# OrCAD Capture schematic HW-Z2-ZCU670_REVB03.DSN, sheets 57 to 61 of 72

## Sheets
57 057 UTIL_3V3 15A Regulator: size Custom
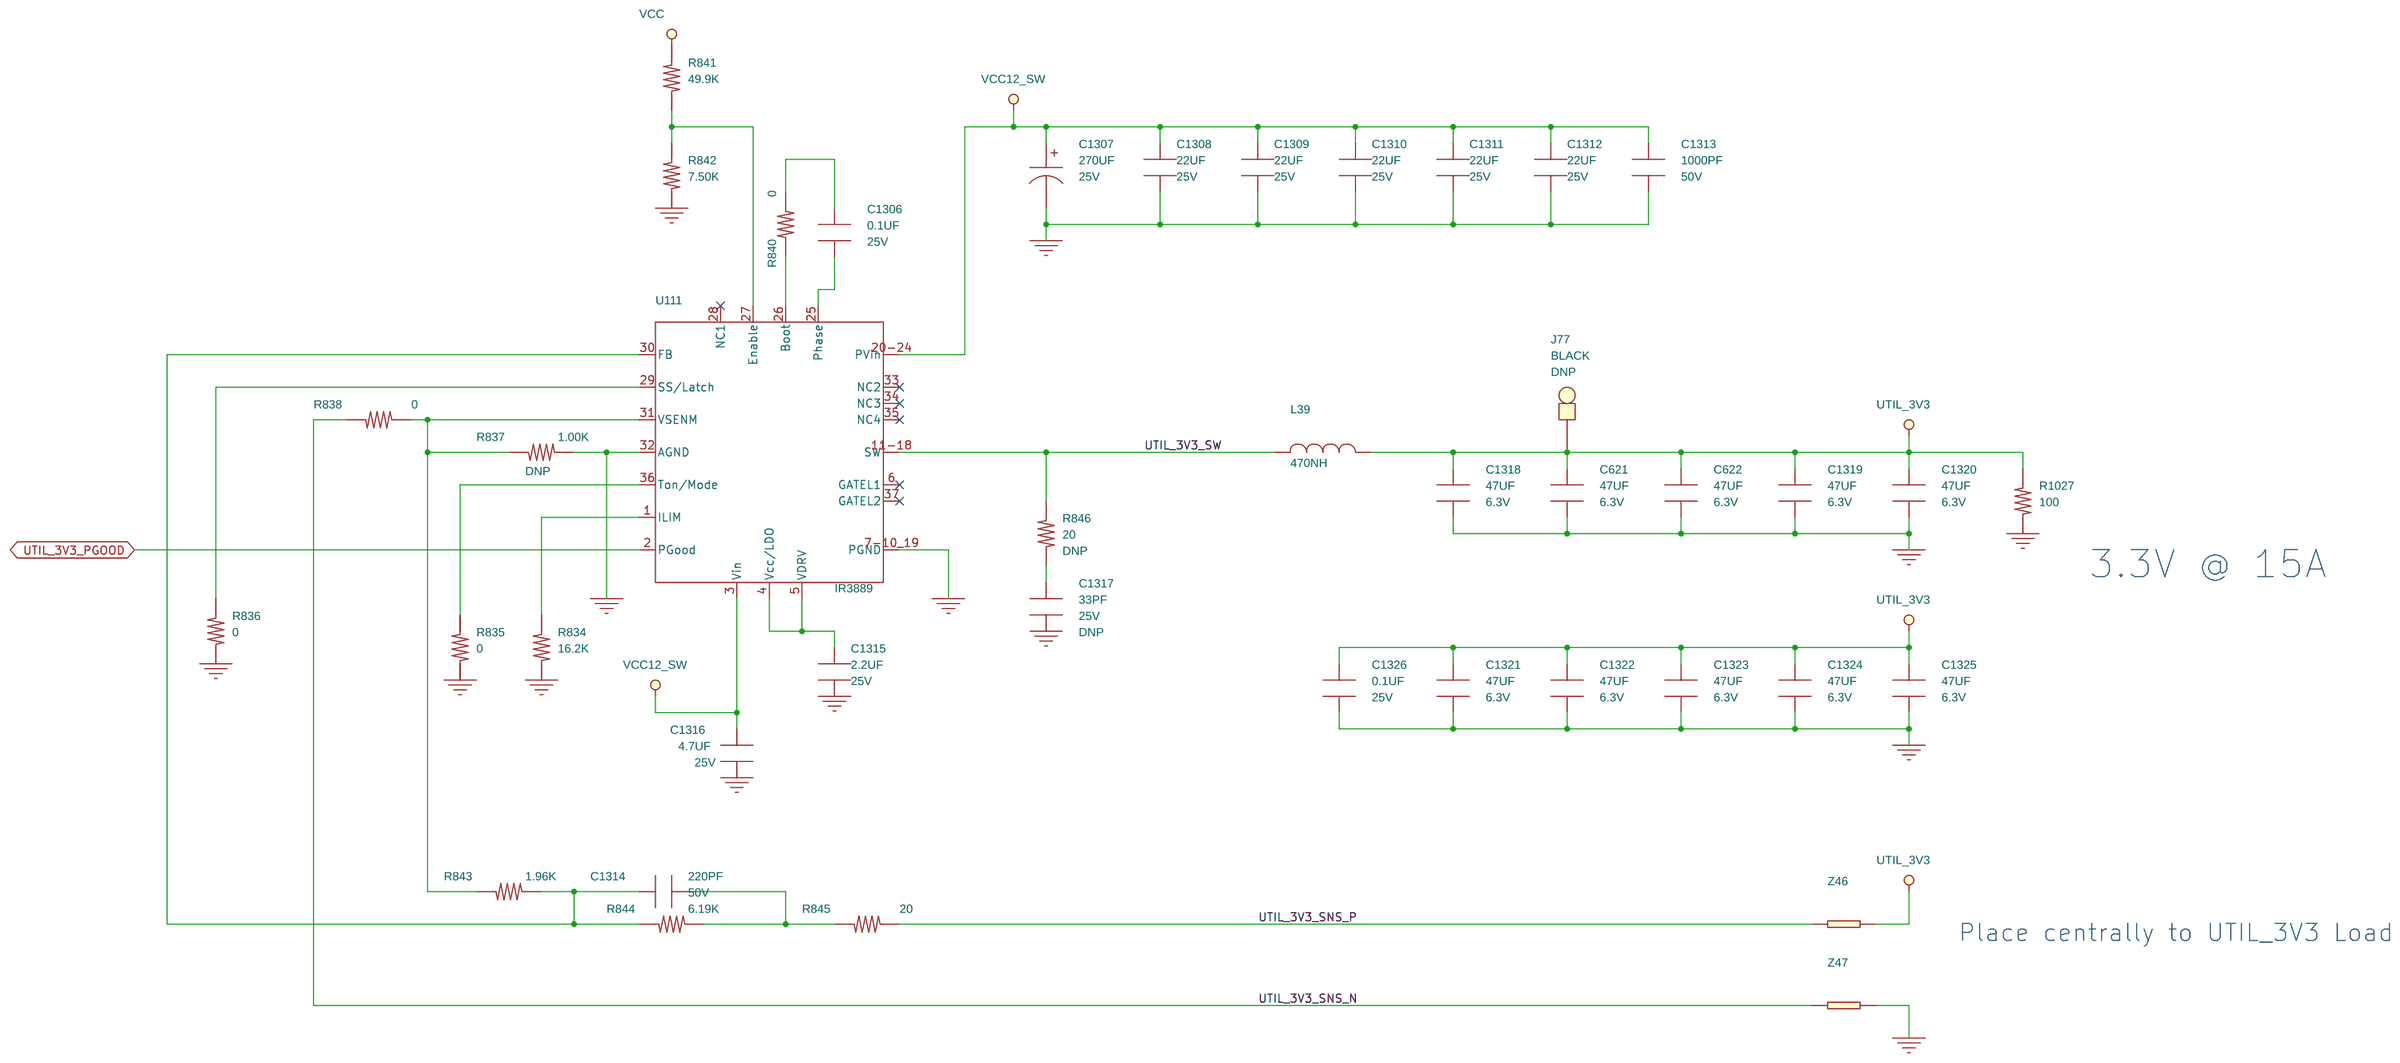
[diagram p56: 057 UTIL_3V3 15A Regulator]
58 058 UTIL_5V0 10A Regulator: size Custom
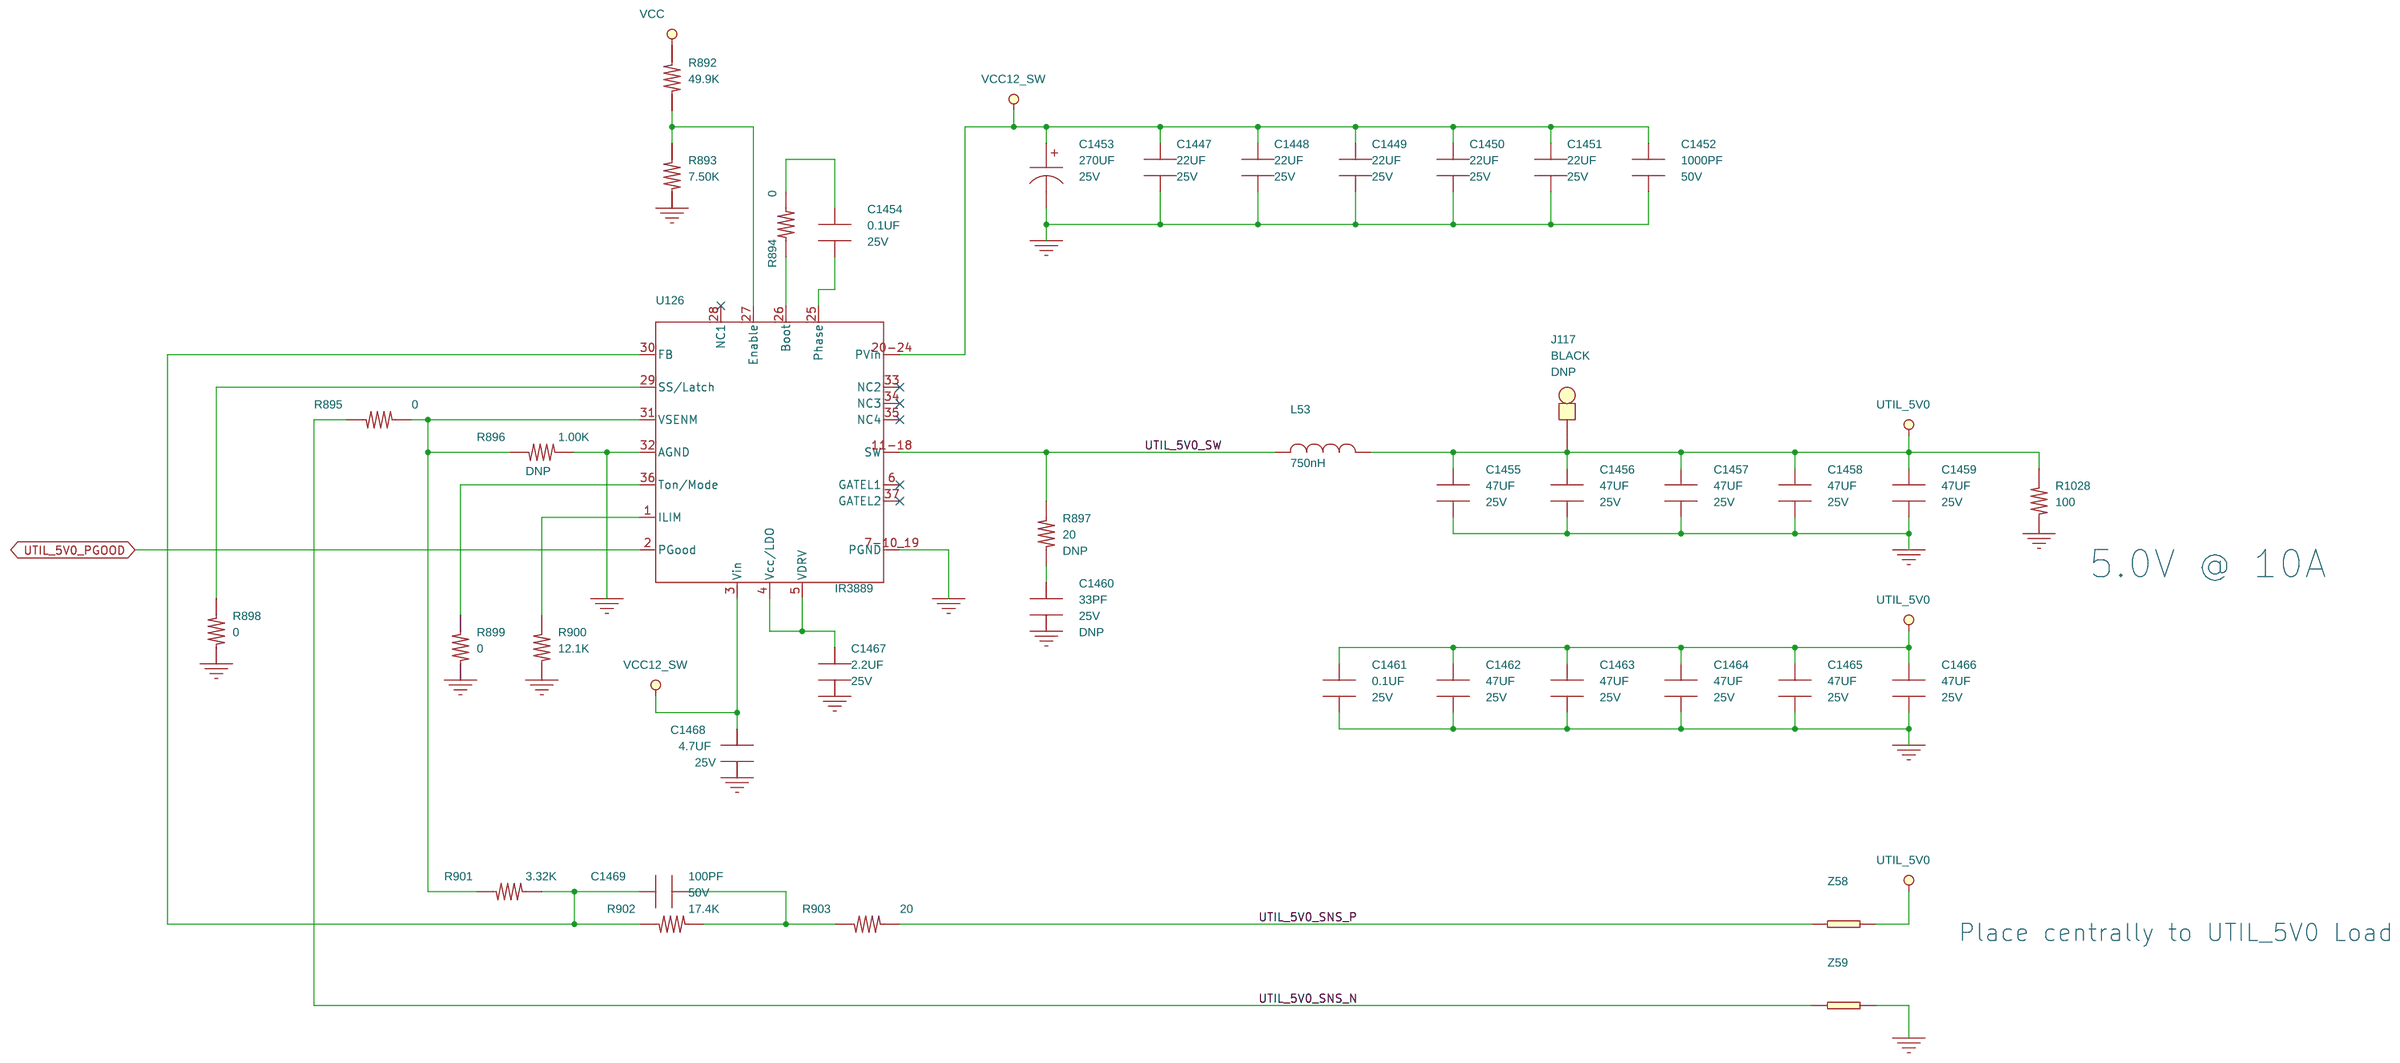
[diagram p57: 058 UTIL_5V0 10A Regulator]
59 059 DDR4 Termination Regulators: size Custom
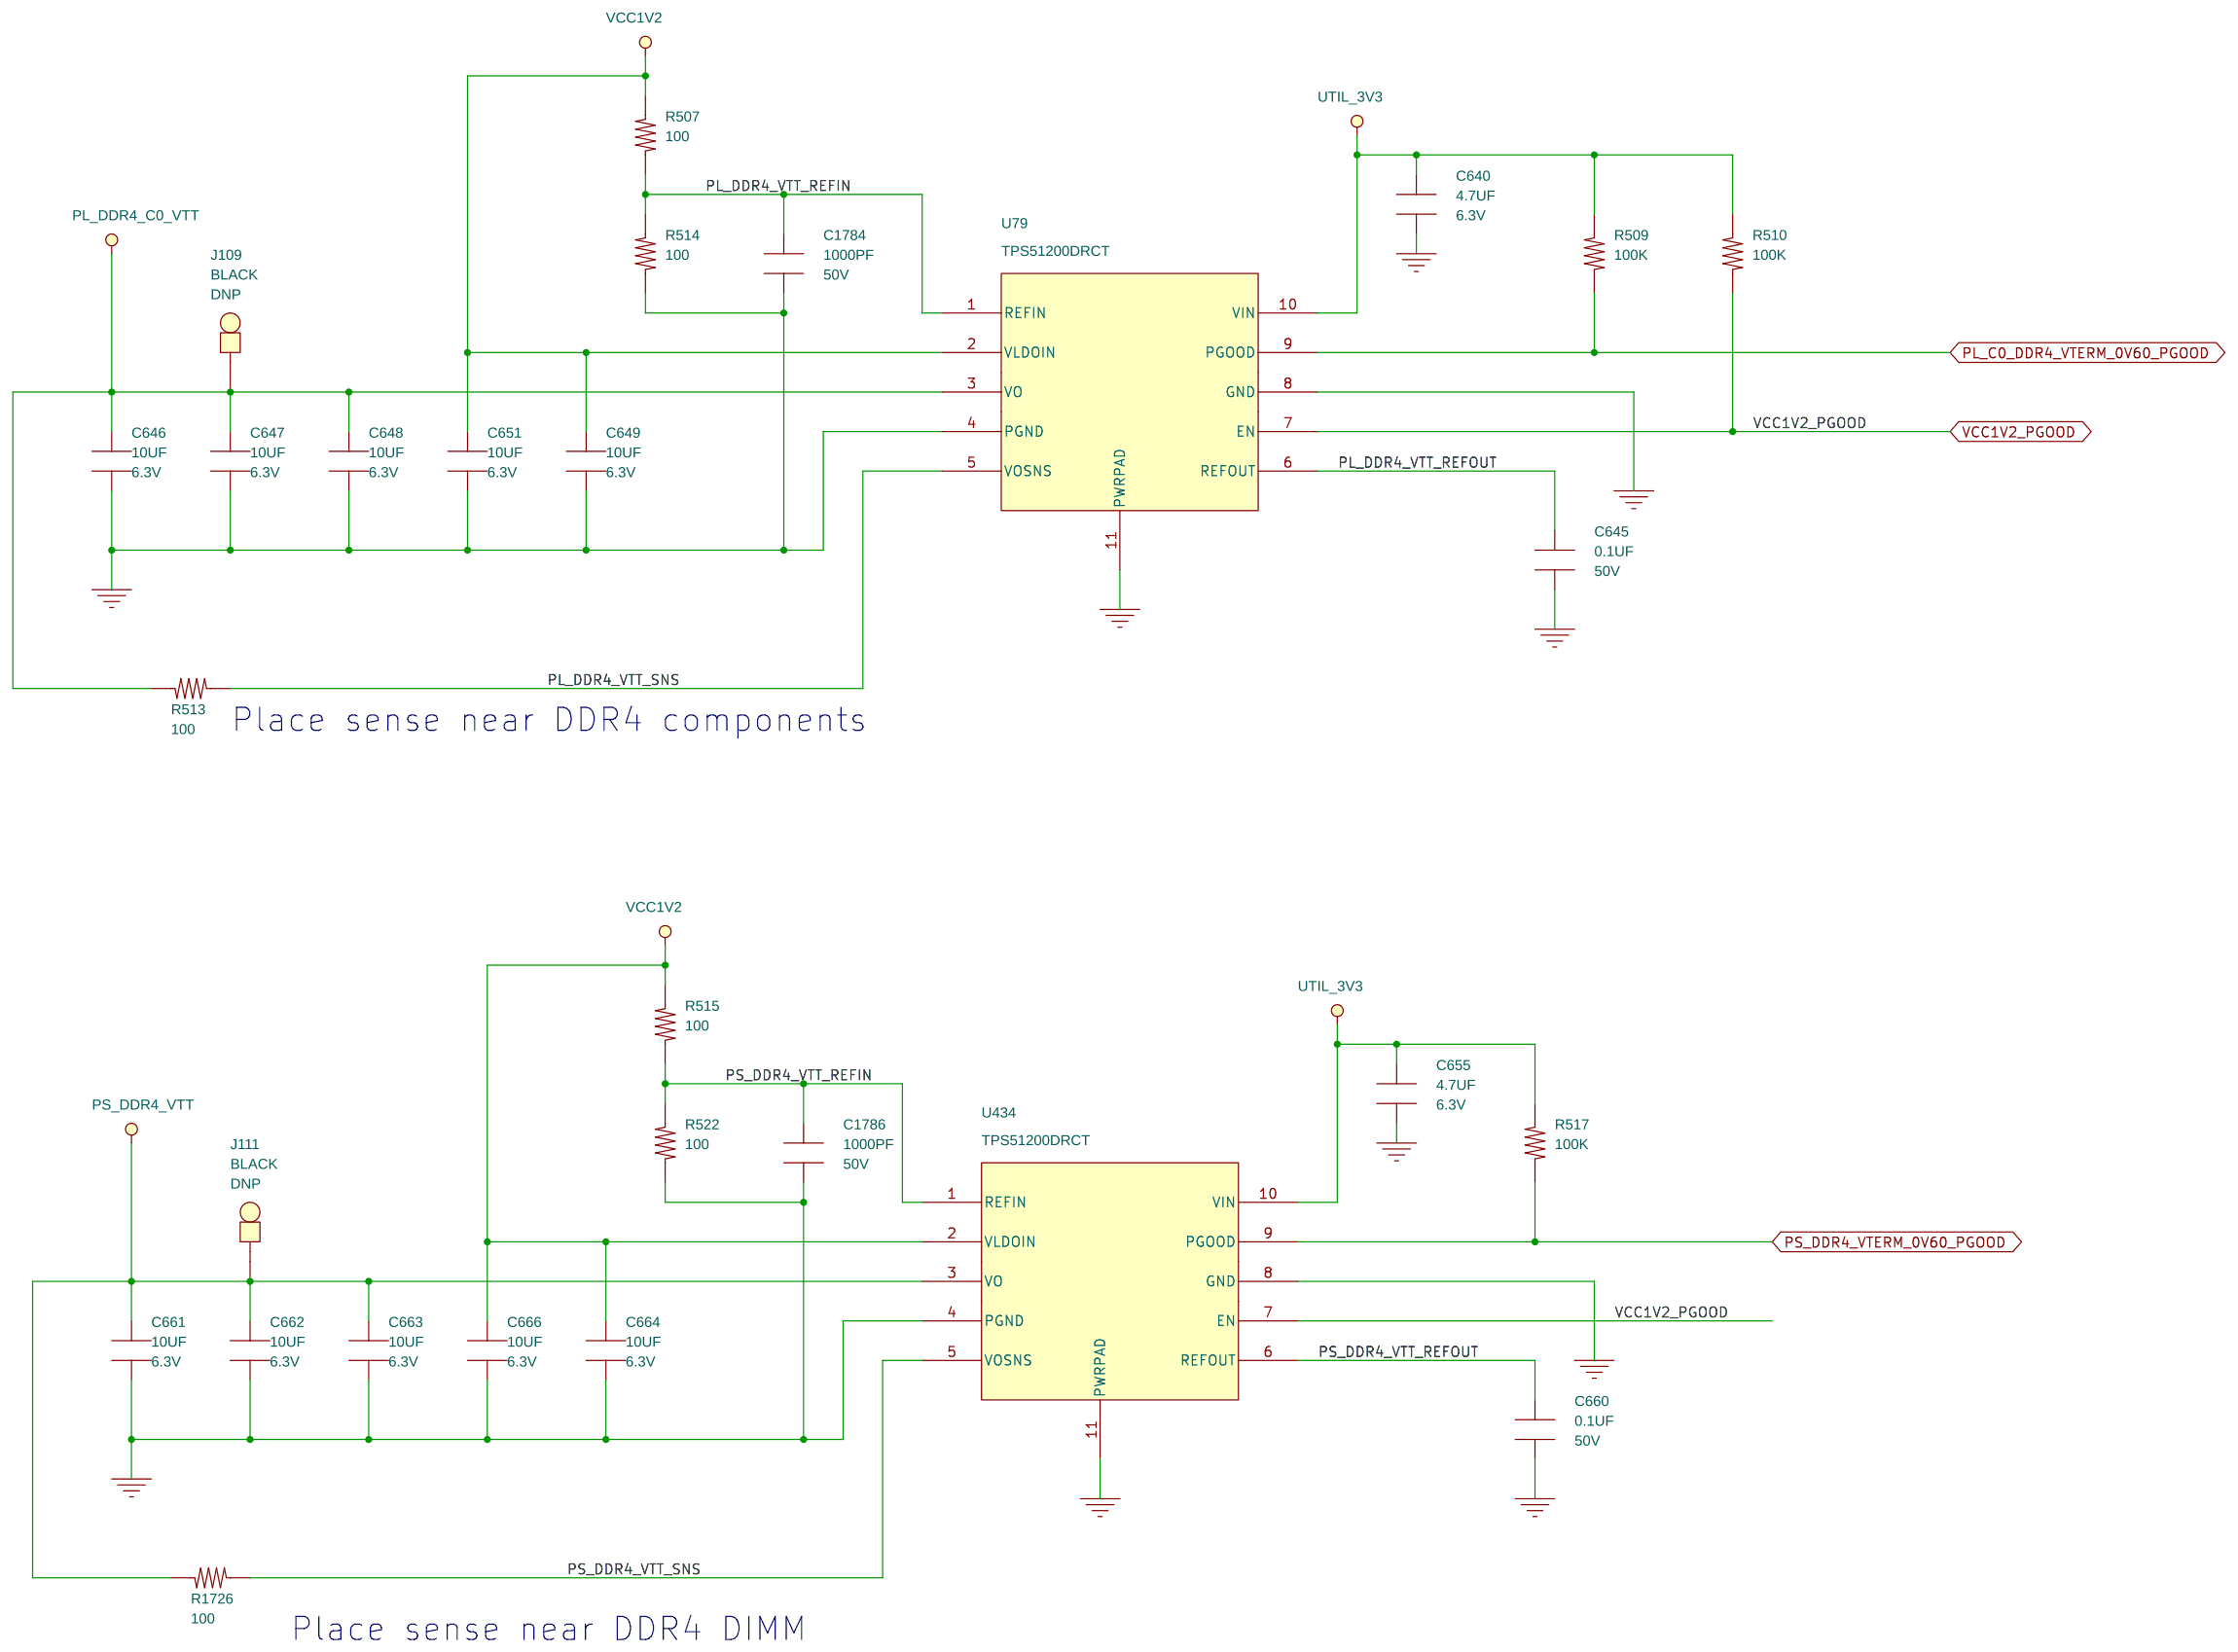
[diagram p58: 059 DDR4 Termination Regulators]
60 060 Power Good LEDs: size Custom
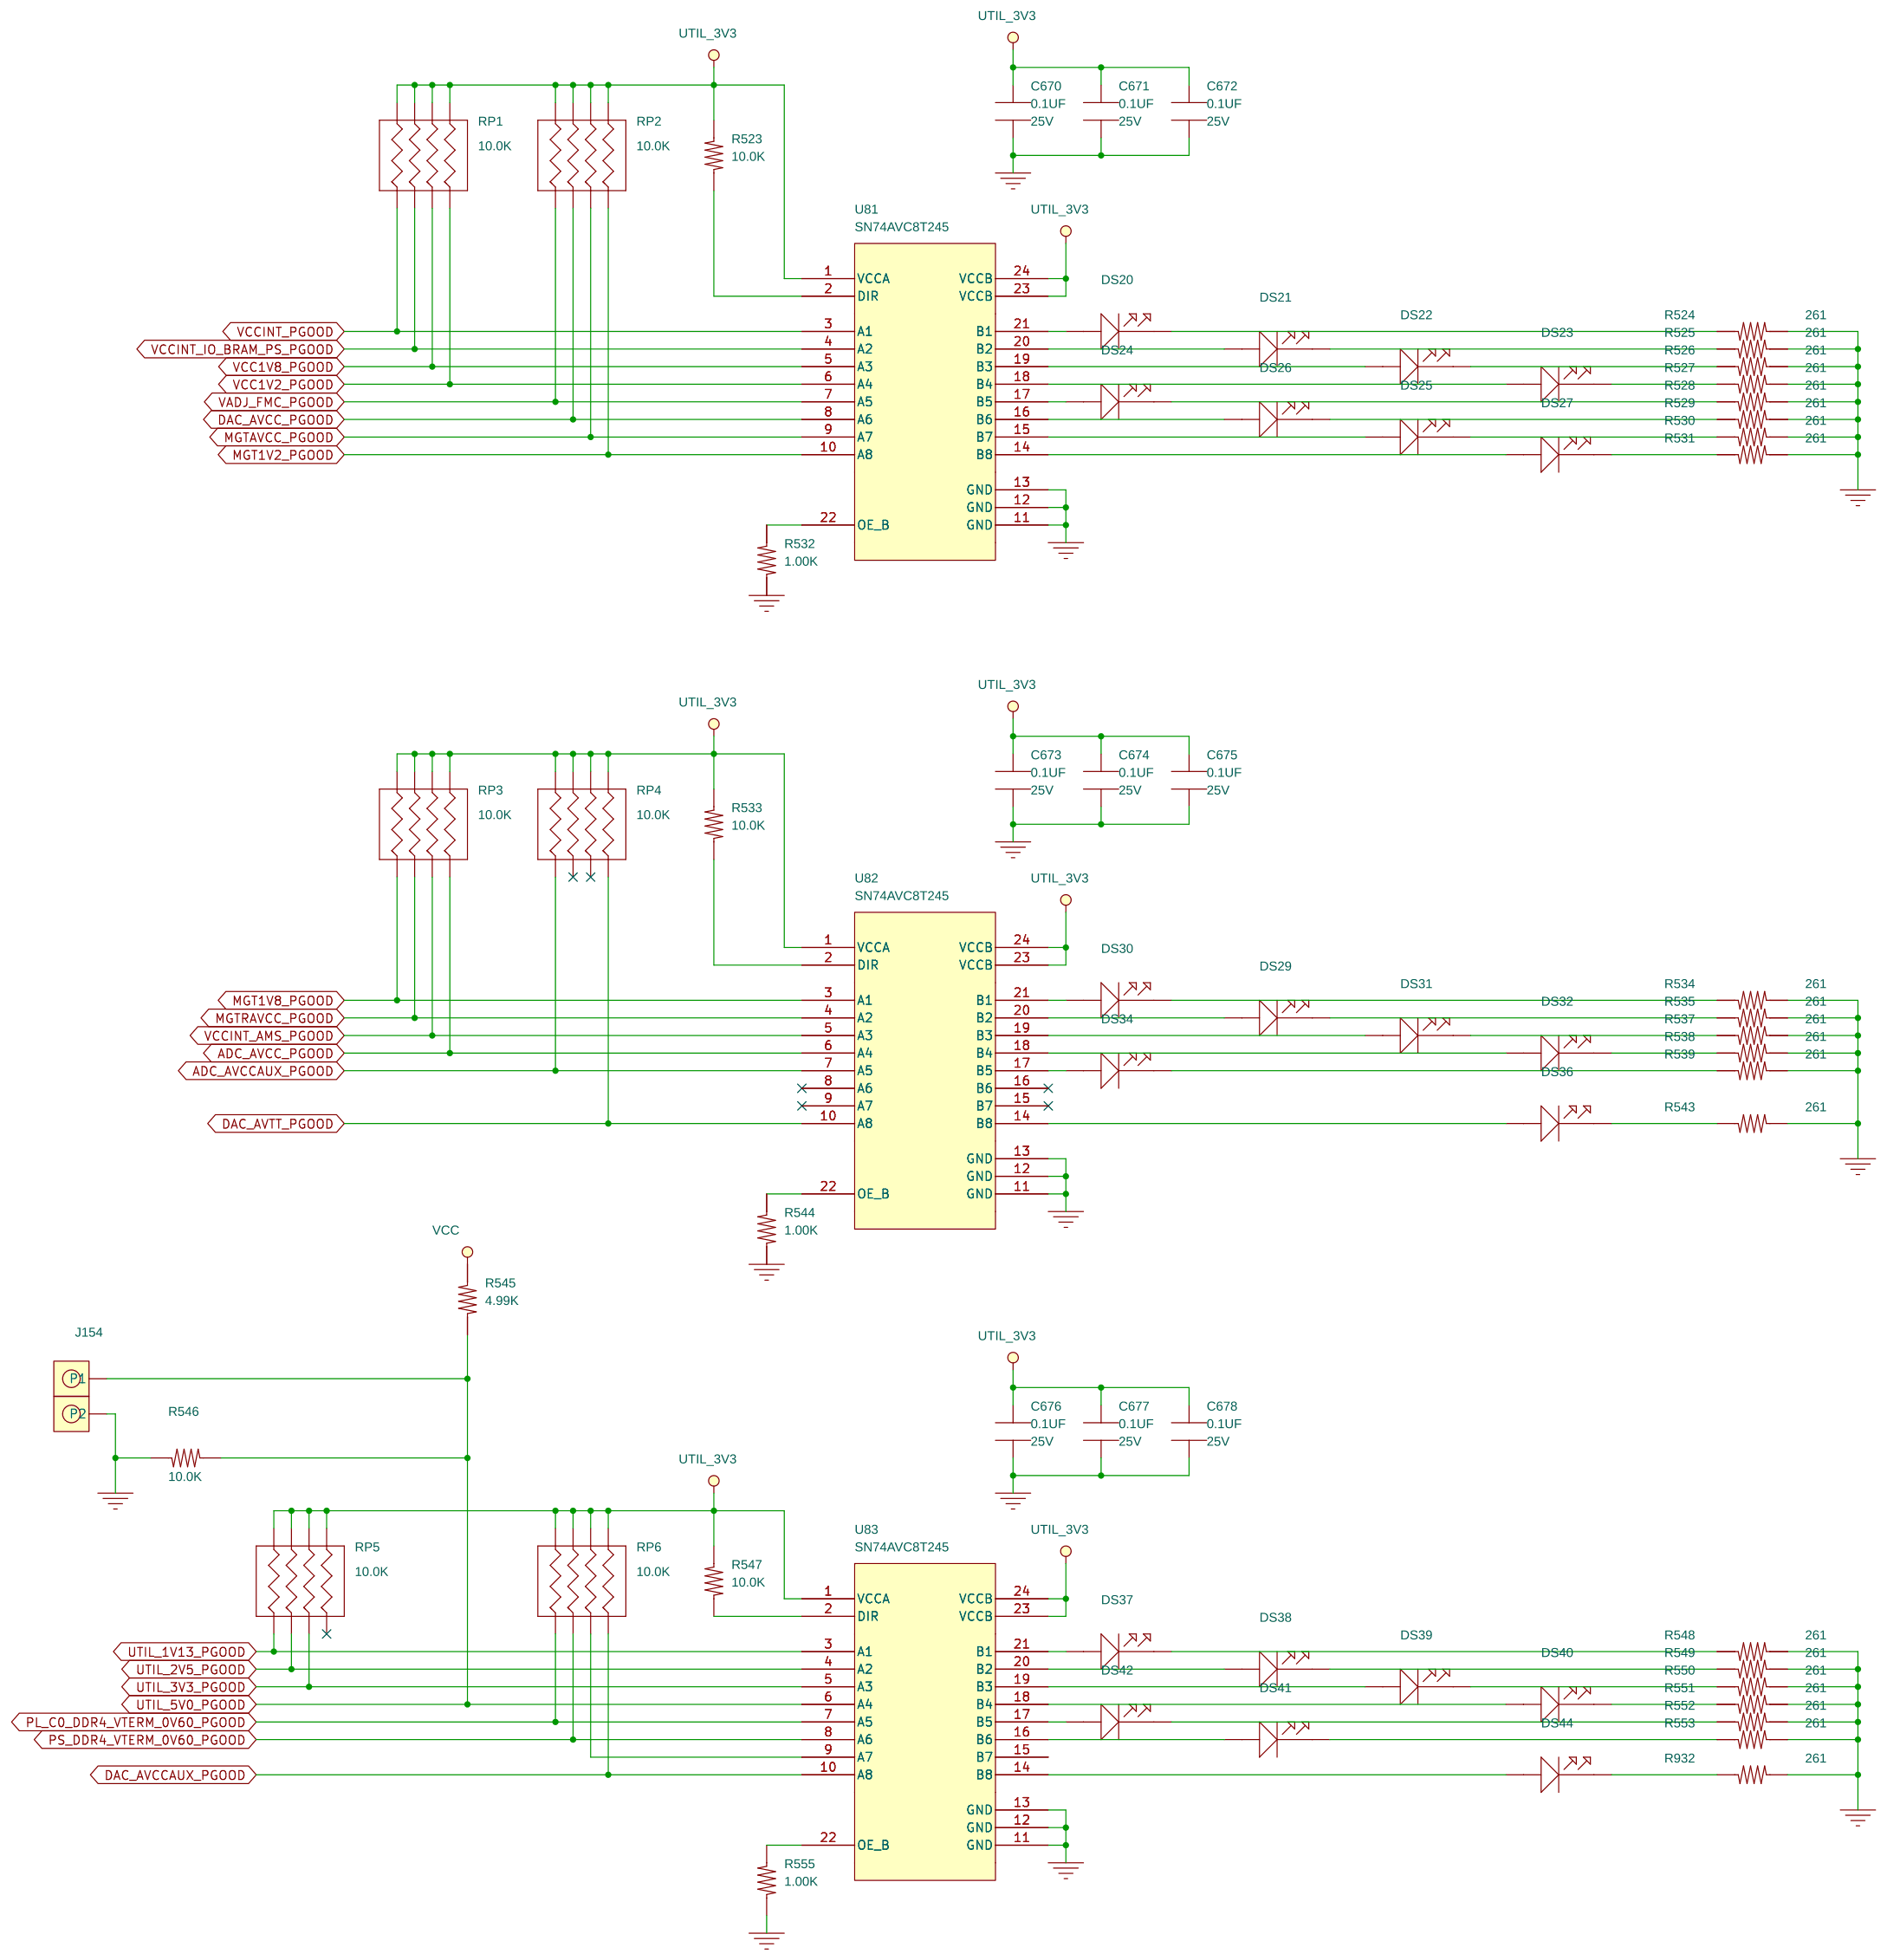
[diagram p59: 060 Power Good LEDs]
61 061 RFMC 2.0 Connector 1: size Custom
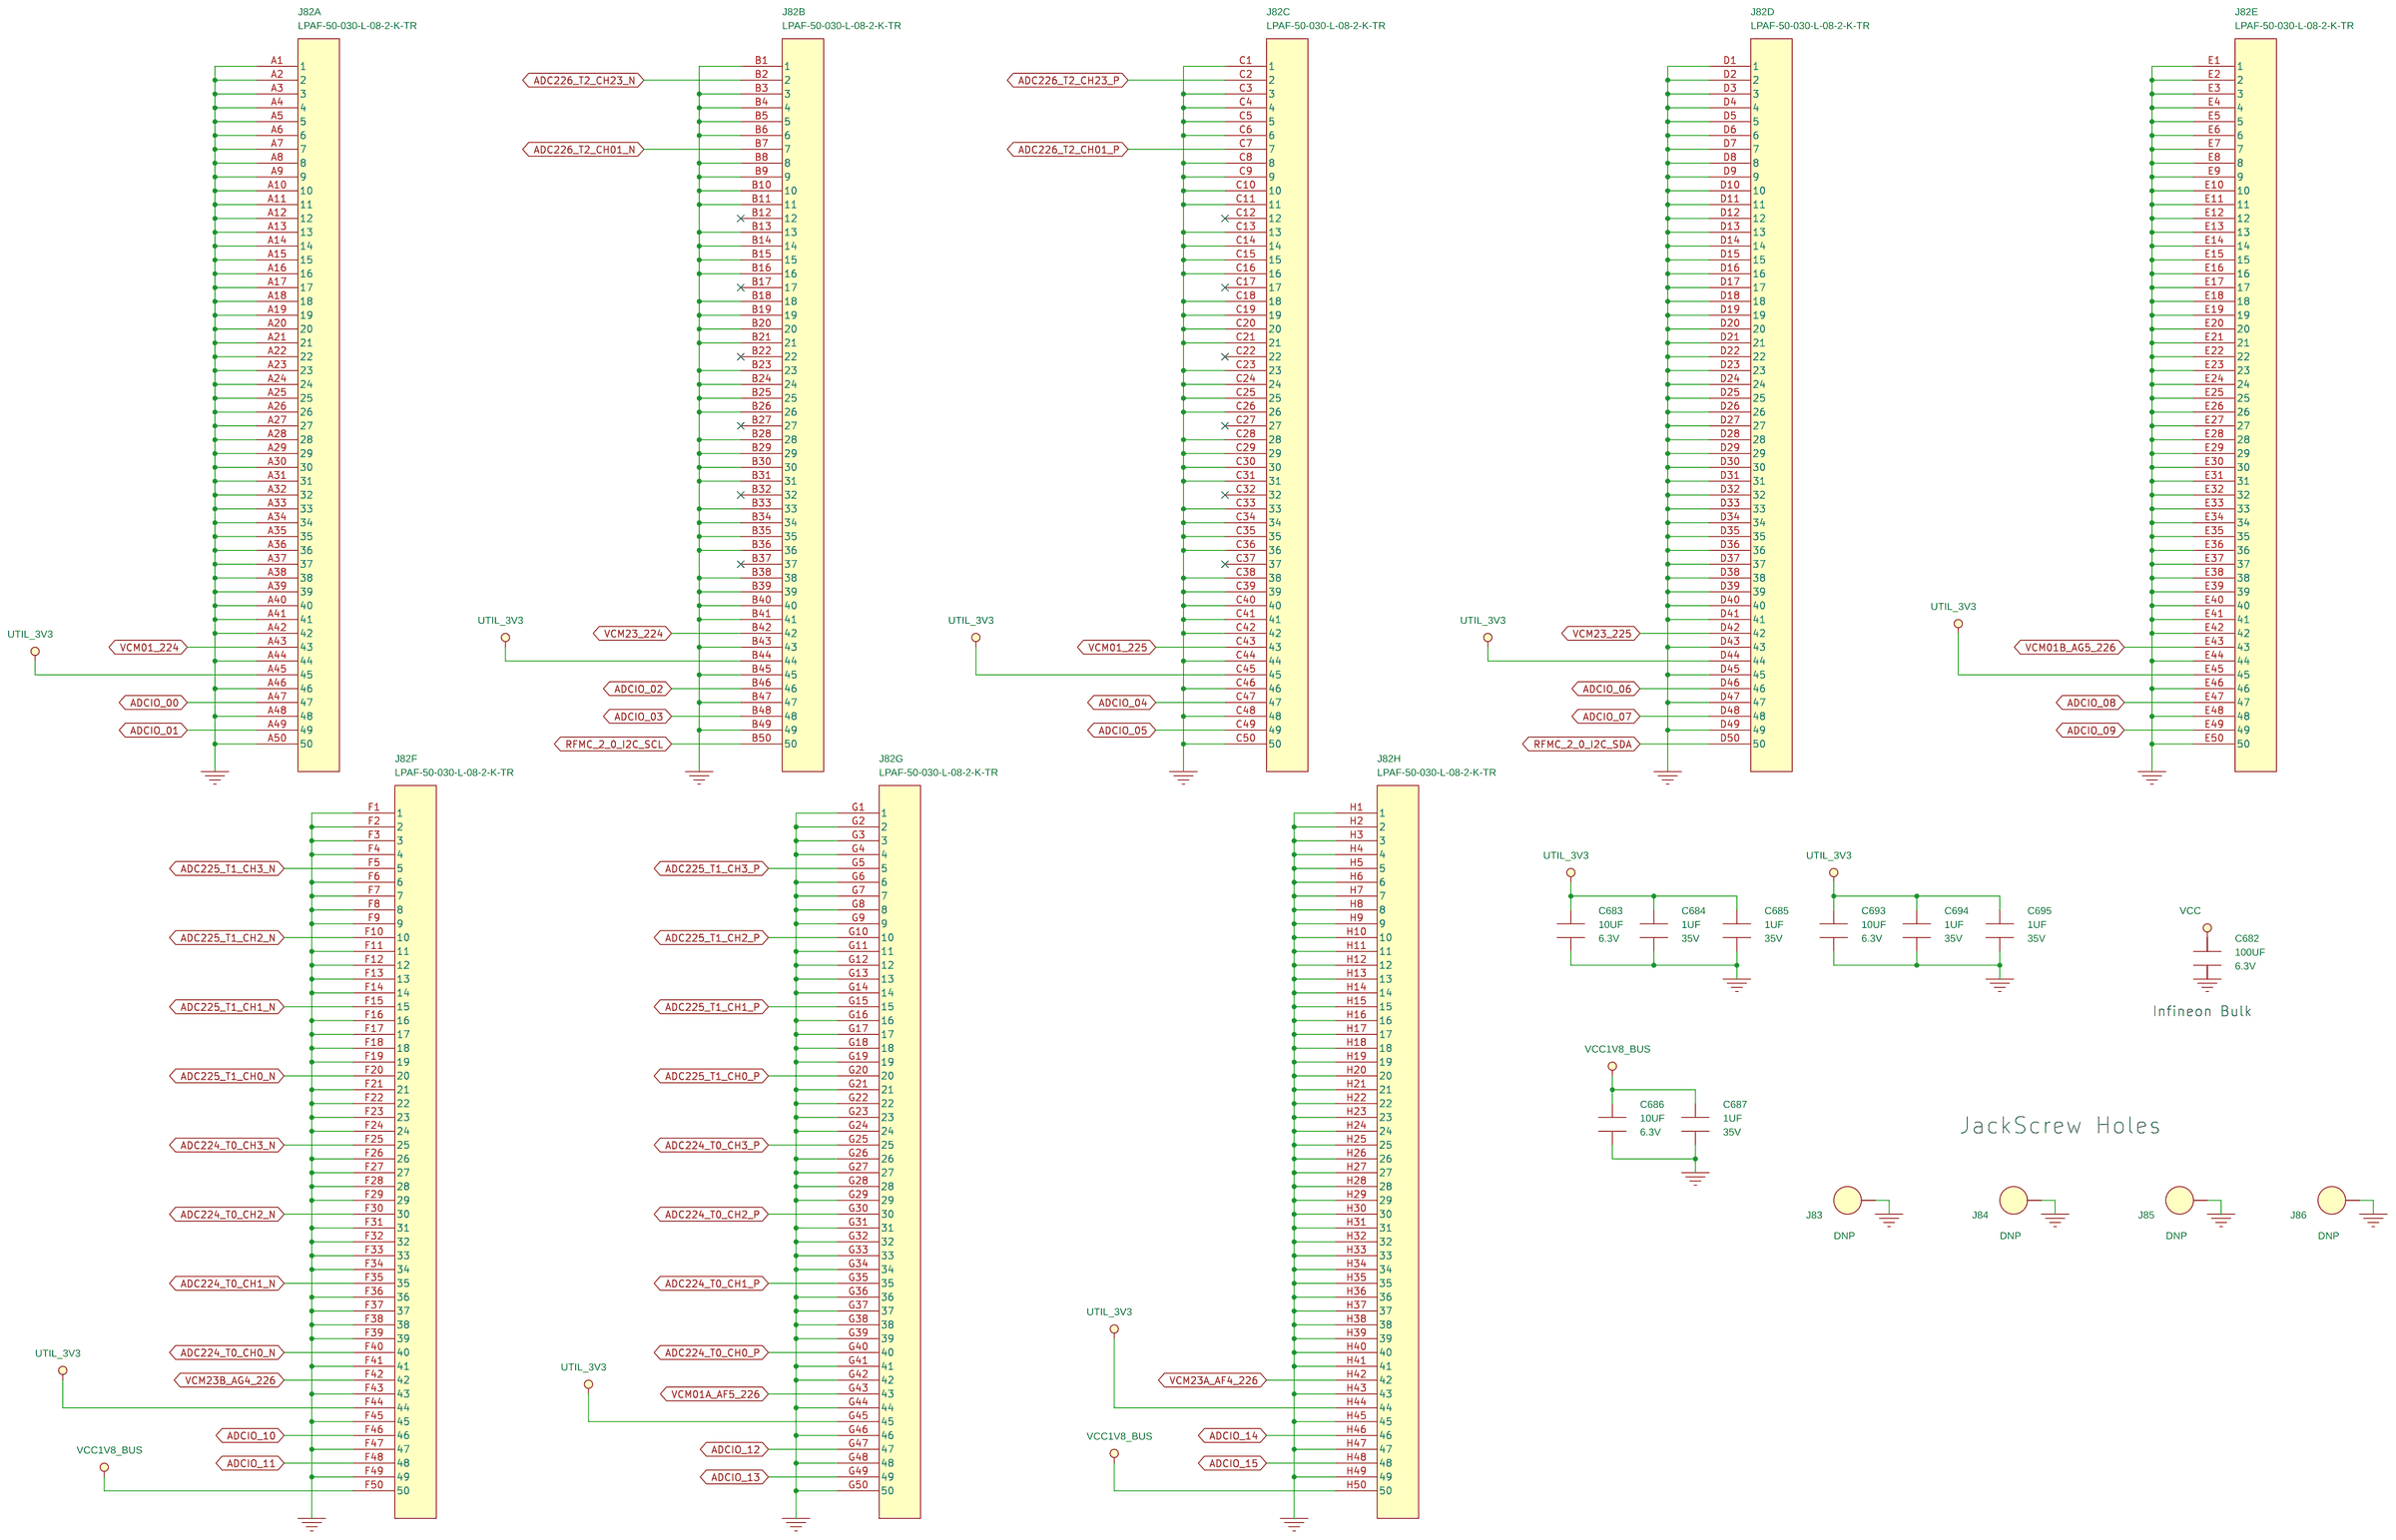
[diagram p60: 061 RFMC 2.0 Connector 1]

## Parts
sheet 057 UTIL_3V3 15A Regulator
C621  47UF  [CAPC200X125X145]
C622  47UF  [CAPC200X125X145]
C1306  0.1UF  [CAPC100X50X55]
C1307  270UF  [CAPR_800_350]
C1308  22UF  [CAPC320X160X180]
C1309  22UF  [CAPC320X160X180]
C1310  22UF  [CAPC320X160X180]
C1311  22UF  [CAPC320X160X180]
C1312  22UF  [CAPC320X160X180]
C1313  1000PF  [CAPC100X50X55]
C1314  220PF  [CAPC100X50X55]
C1315  2.2UF  [CAPC200X125X135]
C1316  4.7UF  [CAPC160X80X100]
C1317  33PF  [CAPC100X50X60]
C1318  47UF  [CAPC200X125X145]
C1319  47UF  [CAPC200X125X145]
C1320  47UF  [CAPC200X125X145]
C1321  47UF  [CAPC200X125X145]
C1322  47UF  [CAPC200X125X145]
C1323  47UF  [CAPC200X125X145]
C1324  47UF  [CAPC200X125X145]
C1325  47UF  [CAPC200X125X145]
C1326  0.1UF  [CAPC100X50X55]
J77  BLACK  [TP_KEY_MINI]
L39  470NH  [IND_WURTH_744355047]
R834  16.2K  [RESC100X50X40]
R835  0  [RESC100X50X40]
R836  0  [RESC100X50X40]
R837  1.00K  [RESC100X50X40]
R838  0  [RESC100X50X40]
R840  0  [RESC100X50X40]
R841  49.9K  [RESC100X50X40]
R842  7.50K  [RESC100X50X40]
R843  1.96K  [RESC100X50X40]
R844  6.19K  [RESC100X50X40]
R845  20  [RESC100X50X40]
R846  20  [RESC100X50X40]
R1027  100  [RESC100X50X40]
U111  IR3889  [QFN_IR3889_36]
Z46  0201_SHORT  [0201_SHORT]
Z47  0201_SHORT  [0201_SHORT]
sheet 058 UTIL_5V0 10A Regulator
C1447  22UF  [CAPC320X160X180]
C1448  22UF  [CAPC320X160X180]
C1449  22UF  [CAPC320X160X180]
C1450  22UF  [CAPC320X160X180]
C1451  22UF  [CAPC320X160X180]
C1452  1000PF  [CAPC100X50X55]
C1453  270UF  [CAPR_800_350]
C1454  0.1UF  [CAPC100X50X55]
C1455  47UF  [CAPC320X160X180]
C1456  47UF  [CAPC320X160X180]
C1457  47UF  [CAPC320X160X180]
C1458  47UF  [CAPC320X160X180]
C1459  47UF  [CAPC320X160X180]
C1460  33PF  [CAPC100X50X60]
C1461  0.1UF  [CAPC100X50X55]
C1462  47UF  [CAPC320X160X180]
C1463  47UF  [CAPC320X160X180]
C1464  47UF  [CAPC320X160X180]
C1465  47UF  [CAPC320X160X180]
C1466  47UF  [CAPC320X160X180]
C1467  2.2UF  [CAPC200X125X135]
C1468  4.7UF  [CAPC160X80X100]
C1469  100PF  [CAPC100X50X55]
J117  BLACK  [TP_KEY_MINI]
L53  750nH  [IND_ABRACON_F1040]
R892  49.9K  [RESC100X50X40]
R893  7.50K  [RESC100X50X40]
R894  0  [RESC100X50X40]
R895  0  [RESC100X50X40]
R896  1.00K  [RESC100X50X40]
R897  20  [RESC100X50X40]
R898  0  [RESC100X50X40]
R899  0  [RESC100X50X40]
R900  12.1K  [RESC100X50X40]
R901  3.32K  [RESC100X50X40]
R902  17.4K  [RESC100X50X40]
R903  20  [RESC100X50X40]
R1028  100  [RESC100X50X40]
U126  IR3889  [QFN_IR3889_36]
Z58  0201_SHORT  [0201_SHORT]
Z59  0201_SHORT  [0201_SHORT]
sheet 059 DDR4 Termination Regulators
C640  4.7UF  [CAPC100X50X70]
C645  0.1UF  [CAPC100X50X55]
C646  10UF  [CAPC100X50X70]
C647  10UF  [CAPC100X50X70]
C648  10UF  [CAPC100X50X70]
C649  10UF  [CAPC100X50X70]
C651  10UF  [CAPC100X50X70]
C655  4.7UF  [CAPC100X50X70]
C660  0.1UF  [CAPC100X50X55]
C661  10UF  [CAPC100X50X70]
C662  10UF  [CAPC100X50X70]
C663  10UF  [CAPC100X50X70]
C664  10UF  [CAPC100X50X70]
C666  10UF  [CAPC100X50X70]
C1784  1000PF  [CAPC100X50X55]
C1786  1000PF  [CAPC100X50X55]
J109  BLACK  [TP_KEY_MINI]
J111  BLACK  [TP_KEY_MINI]
R507  100  [RESC100X50X40]
R509  100K  [RESC100X50X40]
R510  100K  [RESC100X50X40]
R513  100  [RESC60X30X26]
R514  100  [RESC100X50X40]
R515  100  [RESC100X50X40]
R517  100K  [RESC100X50X40]
R522  100  [RESC100X50X40]
R1726  100  [RESC60X30X26]
U79  TPS51200DRCT  [SON50P300X300X100-10TP]
U434  TPS51200DRCT  [SON50P300X300X100-10TP]
sheet 060 Power Good LEDs
C670  0.1UF  [CAPC100X50X55]
C671  0.1UF  [CAPC100X50X55]
C672  0.1UF  [CAPC100X50X55]
C673  0.1UF  [CAPC100X50X55]
C674  0.1UF  [CAPC100X50X55]
C675  0.1UF  [CAPC100X50X55]
C676  0.1UF  [CAPC100X50X55]
C677  0.1UF  [CAPC100X50X55]
C678  0.1UF  [CAPC100X50X55]
DS20  LED-GRN-SMT  [LED_0603]
DS21  LED-GRN-SMT  [LED_0603]
DS22  LED-GRN-SMT  [LED_0603]
DS23  LED-GRN-SMT  [LED_0603]
DS24  LED-GRN-SMT  [LED_0603]
DS25  LED-GRN-SMT  [LED_0603]
DS26  LED-GRN-SMT  [LED_0603]
DS27  LED-GRN-SMT  [LED_0603]
DS29  LED-GRN-SMT  [LED_0603]
DS30  LED-GRN-SMT  [LED_0603]
DS31  LED-GRN-SMT  [LED_0603]
DS32  LED-GRN-SMT  [LED_0603]
DS34  LED-GRN-SMT  [LED_0603]
DS36  LED-GRN-SMT  [LED_0603]
DS37  LED-GRN-SMT  [LED_0603]
DS38  LED-GRN-SMT  [LED_0603]
DS39  LED-GRN-SMT  [LED_0603]
DS40  LED-GRN-SMT  [LED_0603]
DS41  LED-GRN-SMT  [LED_0603]
DS42  LED-GRN-SMT  [LED_0603]
DS44  LED-GRN-SMT  [LED_0603]
J154  HDR_1X2  [HDR_1X2]
R523  10.0K  [RESC100X50X40]
R524  261  [RESC100X50X40]
R525  261  [RESC100X50X40]
R526  261  [RESC100X50X40]
R527  261  [RESC100X50X40]
R528  261  [RESC100X50X40]
R529  261  [RESC100X50X40]
R530  261  [RESC100X50X40]
R531  261  [RESC100X50X40]
R532  1.00K  [RESC100X50X40]
R533  10.0K  [RESC100X50X40]
R534  261  [RESC100X50X40]
R535  261  [RESC100X50X40]
R537  261  [RESC100X50X40]
R538  261  [RESC100X50X40]
R539  261  [RESC100X50X40]
R543  261  [RESC100X50X40]
R544  1.00K  [RESC100X50X40]
R545  4.99K  [RESC100X50X40]
R546  10.0K  [RESC100X50X40]
R547  10.0K  [RESC100X50X40]
R548  261  [RESC100X50X40]
R549  261  [RESC100X50X40]
R550  261  [RESC100X50X40]
R551  261  [RESC100X50X40]
R552  261  [RESC100X50X40]
R553  261  [RESC100X50X40]
R555  1.00K  [RESC100X50X40]
R932  261  [RESC100X50X40]
RP1  10.0K  [RP_EXB_0603x4]
RP2  10.0K  [RP_EXB_0603x4]
RP3  10.0K  [RP_EXB_0603x4]
RP4  10.0K  [RP_EXB_0603x4]
RP5  10.0K  [RP_EXB_0603x4]
RP6  10.0K  [RP_EXB_0603x4]
U81  SN74AVC8T245  [TSSOP_24]
U82  SN74AVC8T245  [TSSOP_24]
U83  SN74AVC8T245  [TSSOP_24]
sheet 061 RFMC 2.0 Connector 1
C682  100UF  [CAPC320X160X180]
C683  10UF  [CAPC100X50X70]
C684  1UF  [CAPC100X50X60]
C685  1UF  [CAPC100X50X60]
C686  10UF  [CAPC100X50X70]
C687  1UF  [CAPC100X50X60]
C693  10UF  [CAPC100X50X70]
C694  1UF  [CAPC100X50X60]
C695  1UF  [CAPC100X50X60]
J82  LPAF-50-030-L-08-2-K-TR  [SAMTEC_LPAF_50_030_L_08_2_K_TR]  (sections A,B,C,D,E,F,G,H)
J83  JSO_0415_01_PRESS_FIT  [JSO_0415_01_PRESS_FIT]
J84  JSO_0415_01_PRESS_FIT  [JSO_0415_01_PRESS_FIT]
J85  JSO_0415_01_PRESS_FIT  [JSO_0415_01_PRESS_FIT]
J86  JSO_0415_01_PRESS_FIT  [JSO_0415_01_PRESS_FIT]

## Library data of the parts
C621 C622 C1318-C1325 = CAP_NP: Cap Cer 47uF 20% 6.3V X5R 0805; Agile Part Number: CAP-00046-01; CIP Link: http://xsjbrdwin1/CIP-E/Component/Index/All?pn=100005; Dielectric Type: X5R; OWNER: 3709; PRICE: 0.17; Part Type: CERAMIC; PartType: CERAMIC; ROHS: Yes; Tolerance: 20%; Voltage: 6.3V; barcode: 100005
C670-C678 C1306 C1326 C1454 C1461 = CAP_NP: Cap Cer 100nF 10% 25V X5R 0402; ALT_SYMBOLS: CAPC100X50X55RND; Agile Part Number: CAP-00068-01; CIP Link: http://xsjbrdwin1/CIP-E/Component/Index/All?pn=100040; Dielectric Type: X5R; OWNER: 4001; PRICE: 0.01; Part Type: CERAMIC; PartType: CERAMIC; ROHS: Yes; Tolerance: 10%; Voltage: 25V; barcode: 100040
C1307 C1453 = CAP_P: Cap Poly 270uF 20% 25V 16mR 8x12mm TH; Agile Part Number: CAP-00226-01; Barcode: 100300; CIP Link: http://xsjbrdwin1/CIP-E/Component/Index/All?pn=100300; Dielectric Type: ELEC; Equivalent Series Resistance: 16mohms; Part Type: ELECTROLYTIC; Tolerance: 20%; Voltage: 25V
C1308-C1312 C1447-C1451 = CAP_NP: Cap Cer 22uF 10% 25V X5R 1206; ALT_SYMBOLS: CAPC320X160X180RND; Agile Part Number: CAP-00058-01; CIP Link: http://xsjbrdwin1/CIP-E/Component/Index/All?pn=100026; Dielectric Type: X5R; OWNER: 3709; PRICE: 0.17; Part Type: CERAMIC; PartType: CERAMIC; ROHS: Yes; Tolerance: 10%; Voltage: 25V; barcode: 100026
C1313 C1452 C1784 C1786 = CAP_NP: Cap Cer 1nF 10% 50V X7R 0402; ALT_SYMBOLS: CAPC100X50X55RND; Agile Part Number: CAP-00036-01; Barcode: 100013; CIP Link: http://xsjbrdwin1/CIP-E/Component/Index/All?pn=100013; Dielectric Type: X7R; Part Type: CERAMIC; Tolerance: 10%; Voltage: 50V
C1314 = CAP_NP: Cap Cer 220pF 10% 50V X7R 0402; ALT_SYMBOLS: (0402,C402-25,CAPC100X50X55L25NRND,CAPC100X50X55L30NRND,CAPC100X50X55L30N); Agile Part Number: CAP-00141-01; Barcode: 100157; CIP Link: http://xsjbrdwin1/CIP-E/Component/Index/All?pn=100157; Dielectric Type: X7R; Part Type: CERAMIC; Tolerance: 10%; Voltage: 50V
C1315 C1467 = CAP_NP: Cap Cer 2.2uF 10% 25V X7R 0805; ALT_SYMBOLS: CAPC200X125X135RND; Agile Part Number: CAP-00114-01; Barcode: 100124; CIP Link: http://xsjbrdwin1/CIP-E/Component/Index/All?pn=100124; Dielectric Type: X7R; Part Type: CERAMIC; Tolerance: 10%; Voltage: 25V
C1316 C1468 = CAP_NP: Cap Cer 4.7uF 10% 25V X5R 0603; ALT_SYMBOLS: 0603; Agile Part Number: CAP-00182-01; Barcode: 100220; CIP Link: http://xsjbrdwin1/CIP-E/Component/Index/All?pn=100220; Dielectric Type: X5R; Part Type: CERAMIC; Tolerance: 10%; Voltage: 25V
C1317 C1460 = CAP_NP: CAP CER 33PF 25V C0G/NP0 0402; ASSEMBLY_OPTIONS: DNP; Agile Part Number: CAP-00086-01; Barcode: 100069; CIP Link: http://xsjbrdwin1/CIP-E/Component/Index/All?pn=100069; Dielectric Type: NP0; Part Type: CERAMIC; Tolerance: 5%; Voltage: 25V
J77 J109 J111 J117 = TP-HOOK: Conn Test Point Mini Loop Black TH; ALT_SYMBOLS: TP_KEY_MINI_DNP; ASSEMBLY_OPTIONS: DNP; Agile Part Number: CON-00272-01; Barcode: 900015; CIP Link: http://xsjbrdwin1/CIP-E/Component/Index/All?pn=900015; OWNER: 3709; Part Type: TEST POINT; PartType: TEST POINT; Pins: 1PIN; Pitch: 0.04IN; ROHS: Yes
L39 = IND: Ind 470nH 20% 26A Irms 50A Isat 99mR 13.0x12.8mm SMT Shielded; Agile Part Number: IND-00146-01; Barcode: 300262; CIP Link: http://xsjbrdwin1/CIP-E/Component/Index/All?pn=300262; OWNER: 3709; PRICE: 0.5; Part Type: POWER INDUCTOR; PartType: POWER INDUCTOR; ROHS: YES; Tolerance: 20%
R834 = RES: Res 16K2 1% 1/16W 100PPM 50V 0402; Agile Part Number: RES-00202-01; Barcode: 200214; CIP Link: http://xsjbrdwin1/CIP-E/Component/Index/All?pn=200214; Part Type: SMT - 1%; Rated Power: 1/16W; Tolerance: 1%
R835 R836 R838 R840 R894 R895 R898 R899 = RES: Res 0R 50mR 1A 0402; ALT_SYMBOLS: RESC100X50X40RND; Agile Part Number: RES-00010-01; Barcode: 200012; CIP Link: http://xsjbrdwin1/CIP-E/Component/Index/All?pn=200012; Part Type: SMT - 5%; Tolerance: 5%
R837 R896 = RES: Res 1K 1% 1/16W 100PPM 50V 0402; ALT_SYMBOLS: RESC100X50X40RND; ASSEMBLY_OPTIONS: DNP; Agile Part Number: RES-00027-01; Barcode: 200098; CIP Link: http://xsjbrdwin1/CIP-E/Component/Index/All?pn=200098; Part Type: SMT - 1%; Rated Power: 1/16W; Tolerance: 1%
R841 R892 = RES: Res 49K9 1% 1/16W 100PPM 50V 0402; ALT_SYMBOLS: RESC100X50X40RND; Agile Part Number: RES-00390-01; Barcode: 200433; CIP Link: http://xsjbrdwin1/CIP-E/Component/Index/All?pn=200433; Part Type: SMT - 1%; Rated Power: 1/16W; Tolerance: 1%
R842 R893 = RES: Res 7K5 1% 1/16W 100PPM 50V 0402; ALT_SYMBOLS: RESC100X50X40RND; Agile Part Number: RES-00008-01; Barcode: 200211; CIP Link: http://xsjbrdwin1/CIP-E/Component/Index/All?pn=200211; Part Type: SMT - 1%; Rated Power: 1/16W; Tolerance: 1%
R843 = RES: Res 1K96 1% 1/16W 100PPM 50V 0402; Agile Part Number: RES-00131-01; Barcode: 200118; CIP Link: http://xsjbrdwin1/CIP-E/Component/Index/All?pn=200118; Part Type: SMT - 1%; Rated Power: 1/16W; Tolerance: 1%
R844 = RES: Res 6K19 1% 1/16W 100PPM 50V 0402; Agile Part Number: RES-00125-01; Barcode: 200112; CIP Link: http://xsjbrdwin1/CIP-E/Component/Index/All?pn=200112; Part Type: SMT - 1%; Rated Power: 1/16W; Tolerance: 1%
R845 R903 = RES: Res 20R 1% 1/16W 100PPM 50V 0402; ALT_SYMBOLS: RESC100X50X40RND; Agile Part Number: RES-00033-01; Barcode: 200119; CIP Link: http://xsjbrdwin1/CIP-E/Component/Index/All?pn=200119; Part Type: SMT - 1%; Rated Power: 1/16W; Tolerance: 1%
R846 R897 = RES: Res 20R 1% 1/16W 100PPM 50V 0402; ALT_SYMBOLS: RESC100X50X40RND; ASSEMBLY_OPTIONS: DNP; Agile Part Number: RES-00033-01; Barcode: 200119; CIP Link: http://xsjbrdwin1/CIP-E/Component/Index/All?pn=200119; Part Type: SMT - 1%; Rated Power: 1/16W; Tolerance: 1%
R1027 R1028 = RES: Res 100R 1% 1/16W 100PPM 50V 0402; ALT_SYMBOLS: RESC100X50X40RND; Agile Part Number: RES-00046-01; Barcode: 200024; CIP Link: http://xsjbrdwin1/CIP-E/Component/Index/All?pn=200024; Part Type: SMT - 1%; Rated Power: 1/16W; Tolerance: 1%
U111 U126 = IR3889: IC V. Reg Step-Down DC/DC Synch 17V 30A 2MHz PQFN-36; Agile Part Number: ICS-00511-01; Barcode: 50000037; CIP Link: http://xsjbrdwin1/CIP-E/Component/Index/All?pn=50000037; Part Type: Integrated Circuits (ICs)\--
Z46 Z47 Z58 Z59 = 0201_SHORT: PCB only 0201_SHORT; ASSEMBLY_OPTIONS: DNP; Barcode: 96000001; CIP Link: http://xsjbrdwin1/CIP-E/Component/Index/All?pn=96000001; OWNER: 3670; Part Type: PCB LAYOUT; PartType: PCB LAYOUT; ROHS: 0
C1455-C1459 C1462-C1466 = CAP_NP: Cap Cer 47uF 20% 25V X5R 1206; ALT_SYMBOLS: CAPC320X160X180RND; Agile Part Number: CAP-00092-01; CIP Link: http://xsjbrdwin1/CIP-E/Component/Index/All?pn=100087; Dielectric Type: X5R; OWNER: 3709; PRICE: 0.17; Part Type: CERAMIC; PartType: CERAMIC; ROHS: Yes; Tolerance: 20%; Voltage: 25V; barcode: 100087
C1469 = CAP_NP: Cap Cer 100pF 5% 50V C0G 0402; ALT_SYMBOLS: CAPC100X50X55RND; Agile Part Number: CAP-00161-01; Barcode: 100187; CIP Link: http://xsjbrdwin1/CIP-E/Component/Index/All?pn=100187; Dielectric Type: NP0; Part Type: CERAMIC; Tolerance: 5%; Voltage: 50V
L53 = IND: Ind 750nH 20% 22A Irms 39A Isat 2.7mR 11x10mm SMT Molded Shielded AEC-Q200; Agile Part Number: IND-00177-01; Barcode: 30000016; CIP Link: http://xsjbrdwin1/CIP-E/Component/Index/All?pn=30000016; OWNER: 3709; PRICE: 0.5; Part Type: Unassigned Part Type; PartType: POWER INDUCTOR; ROHS: YES; Tolerance: 20%
R900 = RES: Res 12K1 1% 1/16W 100PPM 50V 0402; ALT_SYMBOLS: (0402,C402-25,RESC100X50X40L25NRND); Agile Part Number: RES-00016-01; Barcode: 200225; CIP Link: http://xsjbrdwin1/CIP-E/Component/Index/All?pn=200225; Part Type: SMT - 1%; Rated Power: 1/16W; Tolerance: 1%
R901 = RES: Res 3K32 1% 1/16W 100PPM 50V 0402; ALT_SYMBOLS: RESC100X50X40RND; Agile Part Number: RES-00189-01; Barcode: 200198; CIP Link: http://xsjbrdwin1/CIP-E/Component/Index/All?pn=200198; Part Type: SMT - 1%; Rated Power: 1/16W; Tolerance: 1%
R902 = RES: Res 17K4 1% 1/16W 100PPM 50V 0402; Agile Part Number: RES-00229-01; Barcode: 200245; CIP Link: http://xsjbrdwin1/CIP-E/Component/Index/All?pn=200245; Part Type: SMT - 1%; Rated Power: 1/16W; Tolerance: 1%
C640 C655 = CAP_NP: Cap Cer 4.7uF 20% 6.3V X6S 0402; ALT_SYMBOLS: CAPC100X50X70RND; Agile Part Number: CAP-00023-01; CIP Link: http://xsjbrdwin1/CIP-E/Component/Index/All?pn=100230; DEVICE: 4_7UF_0402_X6S_6.3V; Dielectric: X6S; Dielectric Type: X6S; MANF: MURATA; MANF_P/N: GRM155C80J475MEAAD; OWNER: 3709; PRICE: 0.04; Part Type: CERAMIC; PartType: CERAMIC; ROHS: Yes; Tolerance: 20%; Voltage: 6.3V; barcode: 100230; Datasheet: \\XSJ-SMB\AFX\AFX\BOARD_PROJECTS\LIBRARY\\DATASHEETS\CAPACITOR\GRM155C80J475MEAA-01.pdf
C645 C660 = CAP_NP: Cap Cer 100nF 10% 50V X7R 0402; ALT_SYMBOLS: CAPC100X50X55RND; Agile Part Number: CAP-00022-01; CIP Link: http://xsjbrdwin1/CIP-E/Component/Index/All?pn=100170; DEVICE: 0_1UF_0402_X7R_50V; Dielectric: X7R; Dielectric Type: X7R; MANF: TAIYO YUDEN; MANF_P/N: UMK105B7104KV-FR; OWNER: 6176; PRICE: 0.02; Part Type: CERAMIC; PartType: CERAMIC; ROHS: Yes; Tolerance: 10%; Voltage: 50V; barcode: 100170; Datasheet: \\XSJ-SMB\AFX\AFX\BOARD_PROJECTS\LIBRARY\DATASHEETS\CAPACITOR\MLCC_ALL_E.PDF
C646-C649 C651 C661-C664 C666 = CAP_NP: Cap Cer 10uF 20%  6.3V X6S 0402; ALT_SYMBOLS: CAPC100X50X55RND; Agile Part Number: CAP-00035-01; CIP Link: http://xsjbrdwin1/CIP-E/Component/Index/All?pn=100268; DEVICE: 10UF_0402_X6S_6.3V; Dielectric: X6S; Dielectric Type: X6S; MANF: MURATA; MANF_P/N: GRM155C80J106ME11D; OWNER: 13503; PRICE: 0.03; Part Type: CERAMIC; PartType: CERAMIC; ROHS: Yes; Tolerance: 20%; Voltage: 6.3V; barcode: 100268; Datasheet: \\XSJ-SMB\AFX\AFX\BOARD_PROJECTS\LIBRARY\\DATASHEETS\CAPACITOR\GRM155C80J106ME11-01.PDF
R507 R514 R515 R522 = RES: Res 100R 1% 1/16W 100PPM 50V 0402; ALT_SYMBOLS: RESC100X50X40RND; Agile Part Number: RES-00046-01; Barcode: 200024; CIP Link: http://xsjbrdwin1/CIP-E/Component/Index/All?pn=200024; DEVICE: 100_0402_1P; MANF: PANASONIC; MANF_P/N: ERJ-2RKF1000X; OWNER: 4001; PRICE: 0.02; Part Type: SMT - 1%; PartType: SMT - 1%; Power: 1/10W; ROHS: Yes; Rated Power: 1/16W; Tolerance: 1%; primarykey: 403; Datasheet: \\XSJ-SMB\AFX\AFX\BOARD_PROJECTS\LIBRARY\\DATASHEETS\RESISTOR\PANA_ERJ_1%.PDF
R509 R510 R517 = RES: Res 100K 1% 1/16W 100PPM 50V 0402; ALT_SYMBOLS: RESC100X50X40RND; ASSEMBLY_OPTIONS: DNP; Agile Part Number: RES-00011-01; Barcode: 200026; CIP Link: http://xsjbrdwin1/CIP-E/Component/Index/All?pn=200026; DEVICE: 100K_0402_1P; MANF: PANASONIC; MANF_P/N: ERJ-2RKF1003X; OWNER: 3501; PRICE: 0; Part Type: SMT - 1%; PartType: SMT - 1%; Power: 1/10W; ROHS: Yes; Rated Power: 1/16W; Tolerance: 1%; primarykey: 149; Datasheet: \\XSJ-SMB\AFX\AFX\BOARD_PROJECTS\LIBRARY\\DATASHEETS\RESISTOR\PANA_ERJ_1%.PDF
R513 R1726 = RES: Res 100R 1% 1/20W 200PPM 25V 0201; Agile Part Number: RES-00129-01; Barcode: 200116; CIP Link: http://xsjbrdwin1/CIP-E/Component/Index/All?pn=200116; Part Type: SMT - 1%; Rated Power: 1/20W; Tolerance: 1%
U79 U434 = TPS51200: IC Term Reg DDR 4.5A Source 5.5A Sink VSON-10; ALT_SYMBOLS: SON10_TPS51200; Agile Part Number: ICS-00475-01; Barcode: 740011; CIP Link: http://xsjbrdwin1/CIP-E/Component/Index/All?pn=740011; Part Type: REGULATOR
DS20-DS27 DS29-DS32 DS34 DS36-DS42 DS44 = LED: LED Green Diffused 20mA 5V 570nm 0603; Agile Part Number: DIO-00003-01; Barcode: 300021; CIP Link: http://xsjbrdwin1/CIP-E/Component/Index/All?pn=300021; OWNER: 4001; PRICE: 0.1; Power: 2.2-20MA; ROHS: Yes; Rated Power: 2.2-20MA; Voltage: 2.2V
J154 = HDR_1X2: Conn Hdr Male Vert 2 Pos 1x2 2.54mm P Black TH; Agile Part Number: CON-00037-01; Barcode: 390102; CIP Link: http://xsjbrdwin1/CIP-E/Component/Index/All?pn=390102; OWNER: 4001; PRICE: 0.03; Part Type: HEADER; PartType: HEADER; Pins: 2PINS; Pitch: 0.100; ROHS: Yes
R523 R533 R546 R547 = RES: Res 10K 1% 1/16W 100PPM 50V 0402; ALT_SYMBOLS: RESC100X50X40RND; Agile Part Number: RES-00030-01; Barcode: 200025; CIP Link: http://xsjbrdwin1/CIP-E/Component/Index/All?pn=200025; OWNER: 4001; PRICE: 0; Part Type: SMT - 1%; PartType: SMT - 1%; Power: 1/10W; ROHS: Yes; Rated Power: 1/16W; Tolerance: 1%; primarykey: 1
R524-R531 R534 R535 R537-R539 R543 R548-R553 R932 = RES: Res 261R 1% 1/16W 100PPM 50V 0402; ALT_SYMBOLS: RESC100X50X40RND; Agile Part Number: RES-00086-01; Barcode: 200050; CIP Link: http://xsjbrdwin1/CIP-E/Component/Index/All?pn=200050; OWNER: 3501; PRICE: 0; Part Type: SMT - 1%; PartType: SMT - 1%; Power: 1/10W; ROHS: Yes; Rated Power: 1/16W; Tolerance: 1%; primarykey: 60
R532 R544 R555 = RES: Res 1K 1% 1/16W 100PPM 50V 0402; ALT_SYMBOLS: RESC100X50X40RND; Agile Part Number: RES-00027-01; Barcode: 200098; CIP Link: http://xsjbrdwin1/CIP-E/Component/Index/All?pn=200098; OWNER: 4001; PRICE: 0; Part Type: SMT - 1%; PartType: SMT - 1%; Power: 1/16W; ROHS: Yes; Rated Power: 1/16W; Tolerance: 1%; primarykey: 7
R545 = RES: Res 4K99 1% 1/16W 100PPM 50V 0402; ALT_SYMBOLS: RESC100X50X40RND; Agile Part Number: RES-00004-01; Barcode: 200072; CIP Link: http://xsjbrdwin1/CIP-E/Component/Index/All?pn=200072; OWNER: 10460; PRICE: 0; Part Type: SMT - 1%; PartType: SMT - 1%; Power: 1/10W; ROHS: Yes; Rated Power: 1/16W; Tolerance: 1%; primarykey: 157
RP1-RP6 = RPACK_10K_X4: Res Array 4x 10K 5% 1/16W 200PPM 50V 1206 Concave; Agile Part Number: RES-00123-01; Barcode: 200110; CIP Link: http://xsjbrdwin1/CIP-E/Component/Index/All?pn=200110; OWNER: 3501; PRICE: 0.05; Part Type: RPACK; PartType: RPACK; Power: 1/16W; ROHS: Yes; Rated Power: 1/16W; Tolerance: 5%; primarykey: 142
U81-U83 = SN74AVC8T245: IC Lvl Trans 8-Bit Bidir 320Mbps 1.2-3.6V 50mA TSSOP-24; Agile Part Number: ICS-00050-01; Barcode: 500014; CIP Link: http://xsjbrdwin1/CIP-E/Component/Index/All?pn=500014; Family: BUS TRANSCEIVER; Part Type: BUS TRANSCEIVER; ROHS: Yes
C682 = CAP_NP: Cap Cer 100uF 20% 6.3V X5R 1206; ALT_SYMBOLS: 1206; Agile Part Number: CAP-00061-01; CIP Link: http://xsjbrdwin1/CIP-E/Component/Index/All?pn=100029; Dielectric: X6S; Dielectric Type: X5R; OWNER: 3709; PRICE: 0.41; Part Type: CERAMIC; PartType: CERAMIC; ROHS: Yes; Tolerance: 20%; Voltage: 6.3V; barcode: 100029
C683 C686 C693 = CAP_NP: Cap Cer 10uF 20%  6.3V X6S 0402; ALT_SYMBOLS: CAPC100X50X55RND; Agile Part Number: CAP-00035-01; CIP Link: http://xsjbrdwin1/CIP-E/Component/Index/All?pn=100268; Dielectric: X5R; Dielectric Type: X6S; OWNER: 3670; PRICE: 0.04; Part Type: CERAMIC; PartType: CERAMIC; ROHS: Yes; Tolerance: 20%; Voltage: 6.3V; barcode: 100268
C684 C685 C687 C694 C695 = CAP_NP: Cap Cer 1uF 10% 35V X5R 0402; ALT_SYMBOLS: CAPC100X50X60RND; Agile Part Number: CAP-00165-01; CIP Link: http://xsjbrdwin1/CIP-E/Component/Index/All?pn=100192; Dielectric: X5R; Dielectric Type: X5R; OWNER: 3709; PRICE: 0.04; Part Type: CERAMIC; PartType: CERAMIC; ROHS: Yes; Tolerance: 10%; Voltage: 35V; barcode: 100192
J82 = LPAF-50-030-L-08-2-K-TR: Conn Rcpt Female Vert 400 Pos 8x50 1.27mm P Black SMT; Agile Part Number: CON-00235-01; Barcode: 40000017; CIP Link: http://xsjbrdwin1/CIP-E/Component/Index/All?pn=40000017; Part Type: HEADER; Pitch: 0.8MM; RoHS: YES
J83-J86 = HOLE_JSO: JSO-0415-01 PRESS FIT HOLE; ASSEMBLY_OPTIONS: DNP; Barcode: 96000009; CIP Link: http://xsjbrdwin1/CIP-E/Component/Index/All?pn=96000009; OWNER: 3709; Part Type: HOLE; PartType: PCB LAYOUT; ROHS: 0

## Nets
GND: C621.2 C622.2 C640.2 C645.2 C646.2 C647.2 C648.2 C649.2 C651.2 C655.2 C660.2 C661.2 C662.2 C663.2 C664.2 C666.2 C670.2 C671.2 C672.2 C673.2 C674.2 C675.2 C676.2 C677.2 C678.2 C682.2 C683.2 C684.2 C685.2 C686.2 C687.2 C693.2 C694.2 C695.2 C1307.2 C1308.2 C1309.2 C1310.2 C1311.2 C1312.2 C1313.2 C1315.2 C1316.2 C1317.2 C1318.2 C1319.2 C1320.2 C1321.2 C1322.2 C1323.2 C1324.2 C1325.2 C1326.2 C1447.2 C1448.2 C1449.2 C1450.2 C1451.2 C1452.2 C1453.2 C1455.2 C1456.2 C1457.2 C1458.2 C1459.2 C1460.2 C1461.2 C1462.2 C1463.2 C1464.2 C1465.2 C1466.2 C1467.2 C1468.2 C1784.1 C1786.1 J82.A1(1) J82.A2(2) J82.A3(3) J82.A4(4) J82.A5(5) J82.A6(6) J82.A7(7) J82.A8(8) J82.A9(9) J82.A10(10) J82.A11(11) J82.A12(12) J82.A13(13) J82.A14(14) J82.A15(15) J82.A16(16) J82.A17(17) J82.A18(18) J82.A19(19) J82.A20(20) J82.A21(21) J82.A22(22) J82.A23(23) J82.A24(24) J82.A25(25) J82.A26(26) J82.A27(27) J82.A28(28) J82.A29(29) J82.A30(30) J82.A31(31) J82.A32(32) J82.A33(33) J82.A34(34) J82.A35(35) J82.A36(36) J82.A37(37) J82.A38(38) J82.A39(39) J82.A40(40) J82.A41(41) J82.A42(42) J82.A44(44) J82.A46(46) J82.A48(48) J82.A50(50) J82.B1(1) J82.B3(3) J82.B4(4) J82.B5(5) J82.B6(6) J82.B8(8) J82.B9(9) J82.B10(10) J82.B11(11) J82.B13(13) J82.B14(14) J82.B15(15) J82.B16(16) J82.B18(18) J82.B19(19) J82.B20(20) J82.B21(21) J82.B23(23) J82.B24(24) J82.B25(25) J82.B26(26) J82.B28(28) J82.B29(29) J82.B30(30) J82.B31(31) J82.B33(33) J82.B34(34) J82.B35(35) J82.B36(36) J82.B38(38) J82.B39(39) J82.B40(40) J82.B41(41) J82.B43(43) J82.B45(45) J82.B47(47) J82.B49(49) J82.C1(1) J82.C3(3) J82.C4(4) J82.C5(5) J82.C6(6) J82.C8(8) J82.C9(9) J82.C10(10) J82.C11(11) J82.C13(13) J82.C14(14) J82.C15(15) J82.C16(16) J82.C18(18) J82.C19(19) J82.C20(20) J82.C21(21) J82.C23(23) J82.C24(24) J82.C25(25) J82.C26(26) J82.C28(28) J82.C29(29) J82.C30(30) J82.C31(31) J82.C33(33) J82.C34(34) J82.C35(35) J82.C36(36) J82.C38(38) J82.C39(39) J82.C40(40) J82.C41(41) J82.C42(42) J82.C44(44) J82.C46(46) J82.C48(48) J82.C50(50) J82.D1(1) J82.D2(2) J82.D3(3) J82.D4(4) J82.D5(5) J82.D6(6) J82.D7(7) J82.D8(8) J82.D9(9) J82.D10(10) J82.D11(11) J82.D12(12) J82.D13(13) J82.D14(14) J82.D15(15) J82.D16(16) J82.D17(17) J82.D18(18) J82.D19(19) J82.D20(20) J82.D21(21) J82.D22(22) J82.D23(23) J82.D24(24) J82.D25(25) J82.D26(26) J82.D27(27) J82.D28(28) J82.D29(29) J82.D30(30) J82.D31(31) J82.D32(32) J82.D33(33) J82.D34(34) J82.D35(35) J82.D36(36) J82.D37(37) J82.D38(38) J82.D39(39) J82.D40(40) J82.D41(41) J82.D43(43) J82.D45(45) J82.D47(47) J82.D49(49) J82.E1(1) J82.E2(2) J82.E3(3) J82.E4(4) J82.E5(5) J82.E6(6) J82.E7(7) J82.E8(8) J82.E9(9) J82.E10(10) J82.E11(11) J82.E12(12) J82.E13(13) J82.E14(14) J82.E15(15) J82.E16(16) J82.E17(17) J82.E18(18) J82.E19(19) J82.E20(20) J82.E21(21) J82.E22(22) J82.E23(23) J82.E24(24) J82.E25(25) J82.E26(26) J82.E27(27) J82.E28(28) J82.E29(29) J82.E30(30) J82.E31(31) J82.E32(32) J82.E33(33) J82.E34(34) J82.E35(35) J82.E36(36) J82.E37(37) J82.E38(38) J82.E39(39) J82.E40(40) J82.E41(41) J82.E42(42) J82.E44(44) J82.E46(46) J82.E48(48) J82.E50(50) J82.F1(1) J82.F2(2) J82.F3(3) J82.F4(4) J82.F6(6) J82.F7(7) J82.F8(8) J82.F9(9) J82.F11(11) J82.F12(12) J82.F13(13) J82.F14(14) J82.F16(16) J82.F17(17) J82.F18(18) J82.F19(19) J82.F21(21) J82.F22(22) J82.F23(23) J82.F24(24) J82.F26(26) J82.F27(27) J82.F28(28) J82.F29(29) J82.F31(31) J82.F32(32) J82.F33(33) J82.F34(34) J82.F36(36) J82.F37(37) J82.F38(38) J82.F39(39) J82.F41(41) J82.F43(43) J82.F45(45) J82.F47(47) J82.F49(49) J82.G1(1) J82.G2(2) J82.G3(3) J82.G4(4) J82.G6(6) J82.G7(7) J82.G8(8) J82.G9(9) J82.G11(11) J82.G12(12) J82.G13(13) J82.G14(14) J82.G16(16) J82.G17(17) J82.G18(18) J82.G19(19) J82.G21(21) J82.G22(22) J82.G23(23) J82.G24(24) J82.G26(26) J82.G27(27) J82.G28(28) J82.G29(29) J82.G31(31) J82.G32(32) J82.G33(33) J82.G34(34) J82.G36(36) J82.G37(37) J82.G38(38) J82.G39(39) J82.G41(41) J82.G42(42) J82.G44(44) J82.G46(46) J82.G48(48) J82.G50(50) J82.H1(1) J82.H2(2) J82.H3(3) J82.H4(4) J82.H5(5) J82.H6(6) J82.H7(7) J82.H8(8) J82.H9(9) J82.H10(10) J82.H11(11) J82.H12(12) J82.H13(13) J82.H14(14) J82.H15(15) J82.H16(16) J82.H17(17) J82.H18(18) J82.H19(19) J82.H20(20) J82.H21(21) J82.H22(22) J82.H23(23) J82.H24(24) J82.H25(25) J82.H26(26) J82.H27(27) J82.H28(28) J82.H29(29) J82.H30(30) J82.H31(31) J82.H32(32) J82.H33(33) J82.H34(34) J82.H35(35) J82.H36(36) J82.H37(37) J82.H38(38) J82.H39(39) J82.H40(40) J82.H41(41) J82.H43(43) J82.H45(45) J82.H47(47) J82.H49(49) J83.1 J84.1 J85.1 J86.1 J154.2(P2) R514.2 R522.2 R524.2 R525.2 R526.2 R527.2 R528.2 R529.2 R530.2 R531.2 R532.2 R534.2 R535.2 R537.2 R538.2 R539.2 R543.2 R544.2 R546.1 R548.2 R549.2 R550.2 R551.2 R552.2 R553.2 R555.2 R834.2 R835.2 R836.2 R837.2 R842.2 R893.2 R896.2 R898.2 R899.2 R900.2 R932.2 R1027.2 R1028.2 U79.4(PGND) U79.8(GND) U79.11(PWRPAD) U81.11(GND) U81.12(GND) U81.13(GND) U82.11(GND) U82.12(GND) U82.13(GND) U83.11(GND) U83.12(GND) U83.13(GND) U111.7-10_19(PGND) U111.32(AGND) U126.7-10_19(PGND) U126.32(AGND) U434.4(PGND) U434.8(GND) U434.11(PWRPAD) Z47.2(NET2) Z59.2(NET2) ; also on sheet 3 4 5 7 8 9 10 11 12 13 14 16 17 18 19 20 21 22 23 24 25 26 27 28 32 33 34 35 36 37 38 39 40 41 42 43 44 45 46 47 48 49 50 51 52 53 54 55 56 62 63 64 65 66 67 68 69 70 71 72
VCC1V2: C649.1 C651.1 C664.1 C666.1 R507.1 R515.1 U79.2(VLDOIN) U434.2(VLDOIN) ; also on sheet 4 11 17 25 27 40 41 42 48 65 66 67 68
VCC1V2_PGOOD: R510.2 RP1.4 U79.7(EN) U81.6(A4) U434.7(EN) ; also on sheet 47
VCC1V8_BUS: C686.1 C687.1 J82.F50(50) J82.H50(50) ; also on sheet 4 9 10 12 20 21 22 23 24 25 26 27 34 36 37 38 39 42 52 62 64
VCC1V8_PGOOD: RP1.3 U81.5(A3) ; also on sheet 34 49 52
VCC12_SW: C1307.1 C1308.1 C1309.1 C1310.1 C1311.1 C1312.1 C1313.1 C1316.1 C1447.1 C1448.1 C1449.1 C1450.1 C1451.1 C1452.1 C1453.1 C1468.1 R841.1 R892.1 U111.3(Vin) U111.20-24(PVin) U126.3(Vin) U126.20-24(PVin) ; also on sheet 28 31 43 44 45 47 48 49 50 51 52 62
VCCINT_AMS_PGOOD: RP3.3 U82.5(A3) ; also on sheet 44 53 54
VCCINT_IO_BRAM_PS_PGOOD: RP1.2 U81.4(A2) ; also on sheet 50
VCCINT_PGOOD: RP1.1 U81.3(A1) ; also on sheet 44
ADC224_T0_CH0_N: J82.F40(40) ; also on sheet 7
ADC224_T0_CH0_P: J82.G40(40) ; also on sheet 7
ADC224_T0_CH1_N: J82.F35(35) ; also on sheet 7
ADC224_T0_CH1_P: J82.G35(35) ; also on sheet 7
ADC224_T0_CH2_N: J82.F30(30) ; also on sheet 7
ADC224_T0_CH2_P: J82.G30(30) ; also on sheet 7
ADC224_T0_CH3_N: J82.F25(25) ; also on sheet 7
ADC224_T0_CH3_P: J82.G25(25) ; also on sheet 7
ADC225_T1_CH0_N: J82.F20(20) ; also on sheet 7
ADC225_T1_CH0_P: J82.G20(20) ; also on sheet 7
ADC225_T1_CH1_N: J82.F15(15) ; also on sheet 7
ADC225_T1_CH1_P: J82.G15(15) ; also on sheet 7
ADC225_T1_CH2_N: J82.F10(10) ; also on sheet 7
ADC225_T1_CH2_P: J82.G10(10) ; also on sheet 7
ADC225_T1_CH3_N: J82.F5(5) ; also on sheet 7
ADC225_T1_CH3_P: J82.G5(5) ; also on sheet 7
ADC226_T2_CH01_N: J82.B7(7) ; also on sheet 7
ADC226_T2_CH01_P: J82.C7(7) ; also on sheet 7
ADC226_T2_CH23_N: J82.B2(2) ; also on sheet 7
ADC226_T2_CH23_P: J82.C2(2) ; also on sheet 7
ADC_AVCC_PGOOD: RP3.4 U82.6(A4) ; also on sheet 53
ADC_AVCCAUX_PGOOD: RP4.1 U82.7(A5) ; also on sheet 53 54 55
ADCIO_00: J82.A47(47) ; also on sheet 5
ADCIO_01: J82.A49(49) ; also on sheet 5
ADCIO_02: J82.B46(46) ; also on sheet 5
ADCIO_03: J82.B48(48) ; also on sheet 5
ADCIO_04: J82.C47(47) ; also on sheet 5
ADCIO_05: J82.C49(49) ; also on sheet 5
ADCIO_06: J82.D46(46) ; also on sheet 5
ADCIO_07: J82.D48(48) ; also on sheet 5
ADCIO_08: J82.E47(47) ; also on sheet 4
ADCIO_09: J82.E49(49) ; also on sheet 4
ADCIO_10: J82.F46(46) ; also on sheet 4
ADCIO_11: J82.F48(48) ; also on sheet 4
ADCIO_12: J82.G47(47) ; also on sheet 4
ADCIO_13: J82.G49(49) ; also on sheet 4
ADCIO_14: J82.H46(46) ; also on sheet 4
ADCIO_15: J82.H48(48) ; also on sheet 4
DAC_AVCC_PGOOD: RP2.2 U81.8(A6) ; also on sheet 53
DAC_AVCCAUX_PGOOD: RP6.4 U83.10(A8) ; also on sheet 55
DAC_AVTT_PGOOD: RP4.4 U82.10(A8) ; also on sheet 55
MGT1V2_PGOOD: RP2.4 U81.10(A8) ; also on sheet 47 49
MGT1V8_PGOOD: RP3.1 U82.3(A1) ; also on sheet 47
MGTAVCC_PGOOD: RP2.3 U81.9(A7) ; also on sheet 49 51
MGTRAVCC_PGOOD: RP3.2 U82.4(A2) ; also on sheet 49
PL_C0_DDR4_VTERM_0V60_PGOOD: R509.2 RP6.1 U79.9(PGOOD) U83.7(A5)
PL_DDR4_C0_VTT: C646.1 C647.1 C648.1 J109.1(P1) R513.1 U79.3(VO) ; also on sheet 66 68
PL_DDR4_VTT_REFIN: C1784.2 R507.2 R514.1 U79.1(REFIN)
PL_DDR4_VTT_REFOUT: C645.1 U79.6(REFOUT)
PL_DDR4_VTT_SNS: R513.2 U79.5(VOSNS)
PS_DDR4_VTERM_0V60_PGOOD: R517.2 RP6.2 U83.8(A6) U434.9(PGOOD)
PS_DDR4_VTT: C661.1 C662.1 C663.1 J111.1(P1) R1726.1 U434.3(VO) ; also on sheet 40
PS_DDR4_VTT_REFIN: C1786.2 R515.2 R522.1 U434.1(REFIN)
PS_DDR4_VTT_REFOUT: C660.1 U434.6(REFOUT)
PS_DDR4_VTT_SNS: R1726.2 U434.5(VOSNS)
RFMC_2_0_I2C_SCL: J82.B50(50) ; also on sheet 23
RFMC_2_0_I2C_SDA: J82.D50(50) ; also on sheet 23
UTIL_1V13_PGOOD: RP5.1 U83.3(A1) ; also on sheet 47
UTIL_2V5_PGOOD: RP5.2 U83.4(A2) ; also on sheet 49
UTIL_3V3: C621.1 C622.1 C640.1 C655.1 C670.1 C671.1 C672.1 C673.1 C674.1 C675.1 C676.1 C677.1 C678.1 C682.1 C683.1 C684.1 C685.1 C693.1 C694.1 C695.1 C1318.1 C1319.1 C1320.1 C1321.1 C1322.1 C1323.1 C1324.1 C1325.1 C1326.1 J77.1(P1) J82.A45(45) J82.B44(44) J82.C45(45) J82.D44(44) J82.E45(45) J82.F44(44) J82.G45(45) J82.H44(44) L39.2 R509.1 R510.1 R517.1 R523.1 R533.1 R547.1 R1027.1 RP1.5 RP1.6 RP1.7 RP1.8 RP2.5 RP2.6 RP2.7 RP2.8 RP3.5 RP3.6 RP3.7 RP3.8 RP4.5 RP4.6 RP4.7 RP4.8 RP5.5 RP5.6 RP5.7 RP5.8 RP6.5 RP6.6 RP6.7 RP6.8 U79.10(VIN) U81.1(VCCA) U81.23(VCCB) U81.24(VCCB) U82.1(VCCA) U82.23(VCCB) U82.24(VCCB) U83.1(VCCA) U83.23(VCCB) U83.24(VCCB) U434.10(VIN) Z46.2(NET2) ; also on sheet 9 10 20 22 23 24 25 26 27 28 29 30 31 33 34 36 37 40 42 43 44 45 47 49 51 53 54 55 56 64
UTIL_3V3_PGOOD: RP5.3 U83.5(A3) U111.2(PGood)
UTIL_3V3_SNS_N: R838.1 Z47.1(NET1)
UTIL_3V3_SNS_P: R845.2 Z46.1(NET1)
UTIL_3V3_SW: L39.1 R846.1 U111.11-18(SW)
UTIL_5V0: C1455.1 C1456.1 C1457.1 C1458.1 C1459.1 C1461.1 C1462.1 C1463.1 C1464.1 C1465.1 C1466.1 J117.1(P1) L53.2 R545.1 R1028.1 Z58.2(NET2) ; also on sheet 20 44 45 48 53 54 55 62 64 71 72
UTIL_5V0_PGOOD: J154.1(P1) R545.2 R546.2 U83.6(A4) U126.2(PGood) ; also on sheet 47 48 49 50 51 52
UTIL_5V0_SNS_N: R895.1 Z59.1(NET1)
UTIL_5V0_SNS_P: R903.2 Z58.1(NET1)
UTIL_5V0_SW: L53.1 R897.1 U126.11-18(SW)
VADJ_FMC_PGOOD: RP2.1 U81.7(A5) ; also on sheet 28 47
VCM01_224: J82.A43(43) ; also on sheet 7
VCM01_225: J82.C43(43) ; also on sheet 7
VCM01A_AF5_226: J82.G43(43) ; also on sheet 7
VCM01B_AG5_226: J82.E43(43) ; also on sheet 7
VCM23_224: J82.B42(42) ; also on sheet 7
VCM23_225: J82.D42(42) ; also on sheet 7
VCM23A_AF4_226: J82.H42(42) ; also on sheet 7
VCM23B_AG4_226: J82.F42(42) ; also on sheet 7
N18140088: R523.2 U81.2(DIR)
N18140140: R532.1 U81.22(OE_B)
N18142018: DS27.1 R531.1
N18142021: DS25.1 R530.1
N18142027: DS24.1 R528.1
N18142030: DS23.1 R527.1
N18142033: DS23.2 U81.18(B4)
N18142036: DS22.1 R526.1
N18142039: DS21.1 R525.1
N18142042: DS20.1 R524.1
N18142045: DS20.2 U81.21(B1)
N18142048: DS21.2 U81.20(B2)
N18142051: DS22.2 U81.19(B3)
N18142054: DS24.2 U81.17(B5)
N18142060: DS25.2 U81.15(B7)
N18142063: DS27.2 U81.14(B8)
N18143305: R533.2 U82.2(DIR)
N18143325: R544.1 U82.22(OE_B)
N18143707: DS32.1 R538.1
N18143709: DS34.1 R539.1
N18143717: DS30.2 U82.21(B1)
N18143719: DS30.1 R534.1
N18143721: DS29.1 R535.1
N18143723: DS31.1 R537.1
N18143725: DS32.2 U82.18(B4)
N18143733: DS34.2 U82.17(B5)
N18143735: DS31.2 U82.19(B3)
N18143737: DS29.2 U82.20(B2)
N18148050: R547.2 U83.2(DIR)
N18148072: R555.1 U83.22(OE_B)
N18148444: DS41.1 R553.1
N18148446: DS42.1 R552.1
N18148448: DS40.1 R551.1
N18148460: DS40.2 U83.18(B4)
N18148462: DS39.1 R550.1
N18148464: DS38.1 R549.1
N18148466: DS37.1 R548.1
N18148468: DS37.2 U83.21(B1)
N18148474: DS38.2 U83.20(B2)
N18148476: DS39.2 U83.19(B3)
N18148478: DS42.2 U83.17(B5)
N18148480: DS41.2 U83.16(B6)
N20088414: DS36.1 R543.1
N20088416: DS36.2 U82.14(B8)
N20122955: DS26.1 R529.1
N20122957: DS26.2 U81.16(B6)
N24223726: R900.1 U126.1(ILIM)
N24223728: R899.1 U126.36(Ton/Mode)
N24223730: R898.1 U126.29(SS/Latch)
N24223735: R895.2 R896.1 R901.1 U126.31(VSENM)
N24223742: C1469.1 R901.2 R902.1 U126.30(FB)
N24223747: R894.2 U126.26(Boot)
N24223748: C1454.1 R894.1
N24223751: C1454.2 U126.25(Phase)
N24223754: R892.2 R893.1 U126.27(Enable)
N24223790: C1469.2 R902.2 R903.1
N24223799: C1467.1 U126.4(Vcc/LDO) U126.5(VDRV)
N24223811: C1460.1 R897.2
N24227820: R841.2 R842.1 U111.27(Enable)
N24227888: C1306.1 R840.1
N24228036: R840.2 U111.26(Boot)
N24228038: C1306.2 U111.25(Phase)
N24228072: C1314.1 R843.2 R844.1 U111.30(FB)
N24228078: R836.1 U111.29(SS/Latch)
N24228106: R837.1 R838.2 R843.1 U111.31(VSENM)
N24228180: R835.1 U111.36(Ton/Mode)
N24228254: R834.1 U111.1(ILIM)
N24228303: C1317.1 R846.2
N24228309: C1315.1 U111.4(Vcc/LDO) U111.5(VDRV)
N24228598: C1314.2 R844.2 R845.1
N25929068: RP6.3 U83.9(A7)
N25930391: DS44.2 U83.14(B8)
N25930393: DS44.1 R932.1

Not connected (* = marked no-connect by the designer): J82 B12(12)* B17(17)* B22(22)* B27(27)* B32(32)* B37(37)* C12(12)* C17(17)* C22(22)* C27(27)* C32(32)* C37(37)*; RP4 2* 3*; RP5 4*; U82 8(A6)* 9(A7)* 15(B7)* 16(B6)*; U83 15(B7); U111 6(GATEL1)* 28(NC1)* 33(NC2)* 34(NC3)* 35(NC4)* 37(GATEL2)*; U126 6(GATEL1)* 28(NC1)* 33(NC2)* 34(NC3)* 35(NC4)* 37(GATEL2)*

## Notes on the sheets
sheet 57
- 3.3V @ 15A
- Place centrally to UTIL_3V3 Load
sheet 58
- 5.0V @ 10A
- Place centrally to UTIL_5V0 Load
sheet 59
- Place sense near DDR4 components
- Place sense near DDR4 DIMM
sheet 61
- Infineon Bulk
- JackScrew Holes
